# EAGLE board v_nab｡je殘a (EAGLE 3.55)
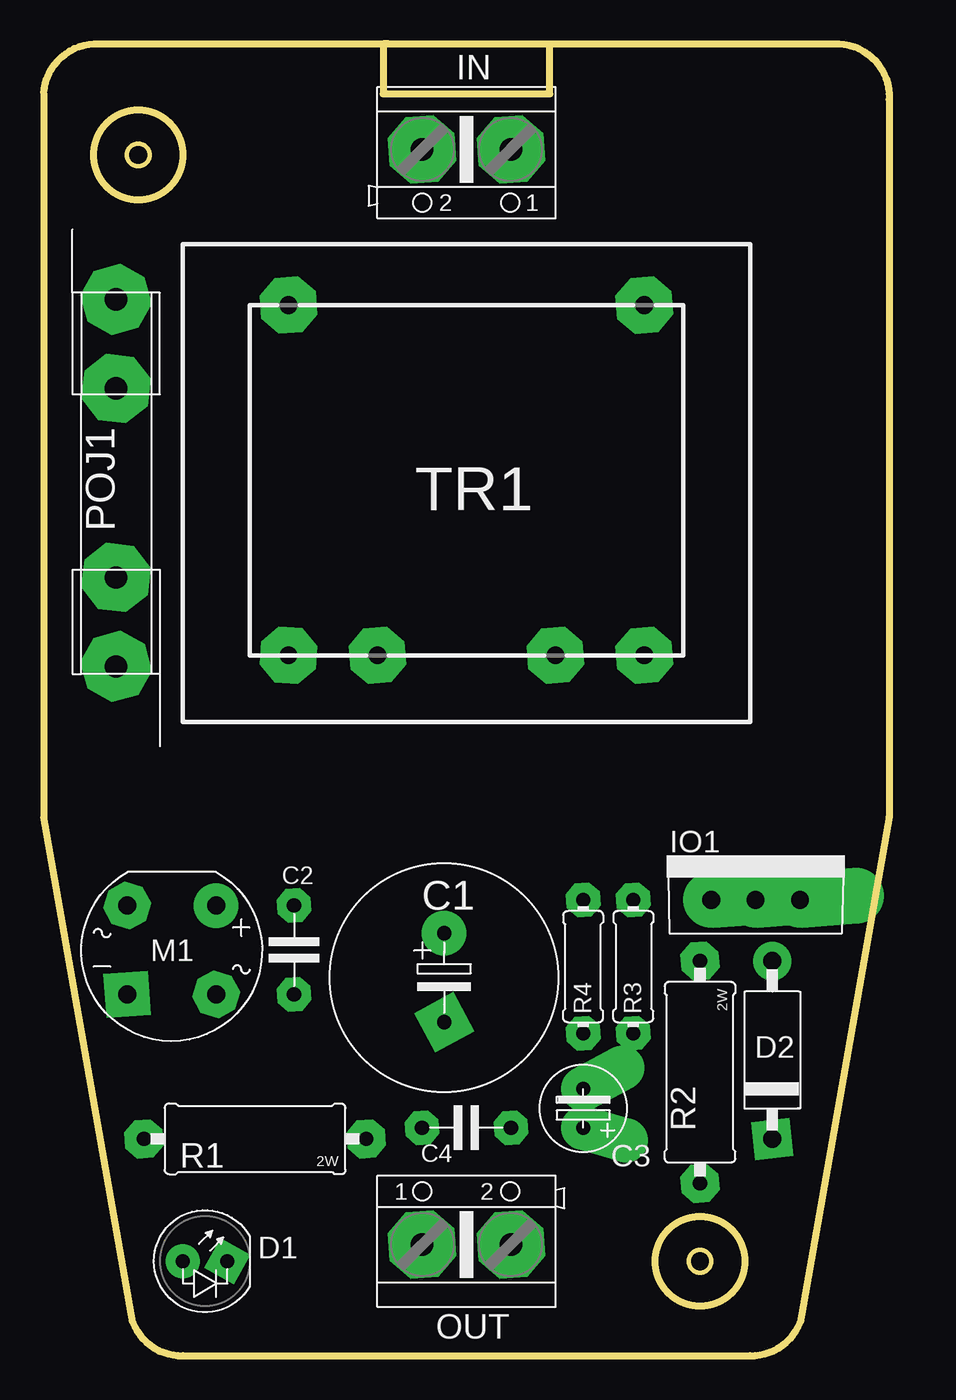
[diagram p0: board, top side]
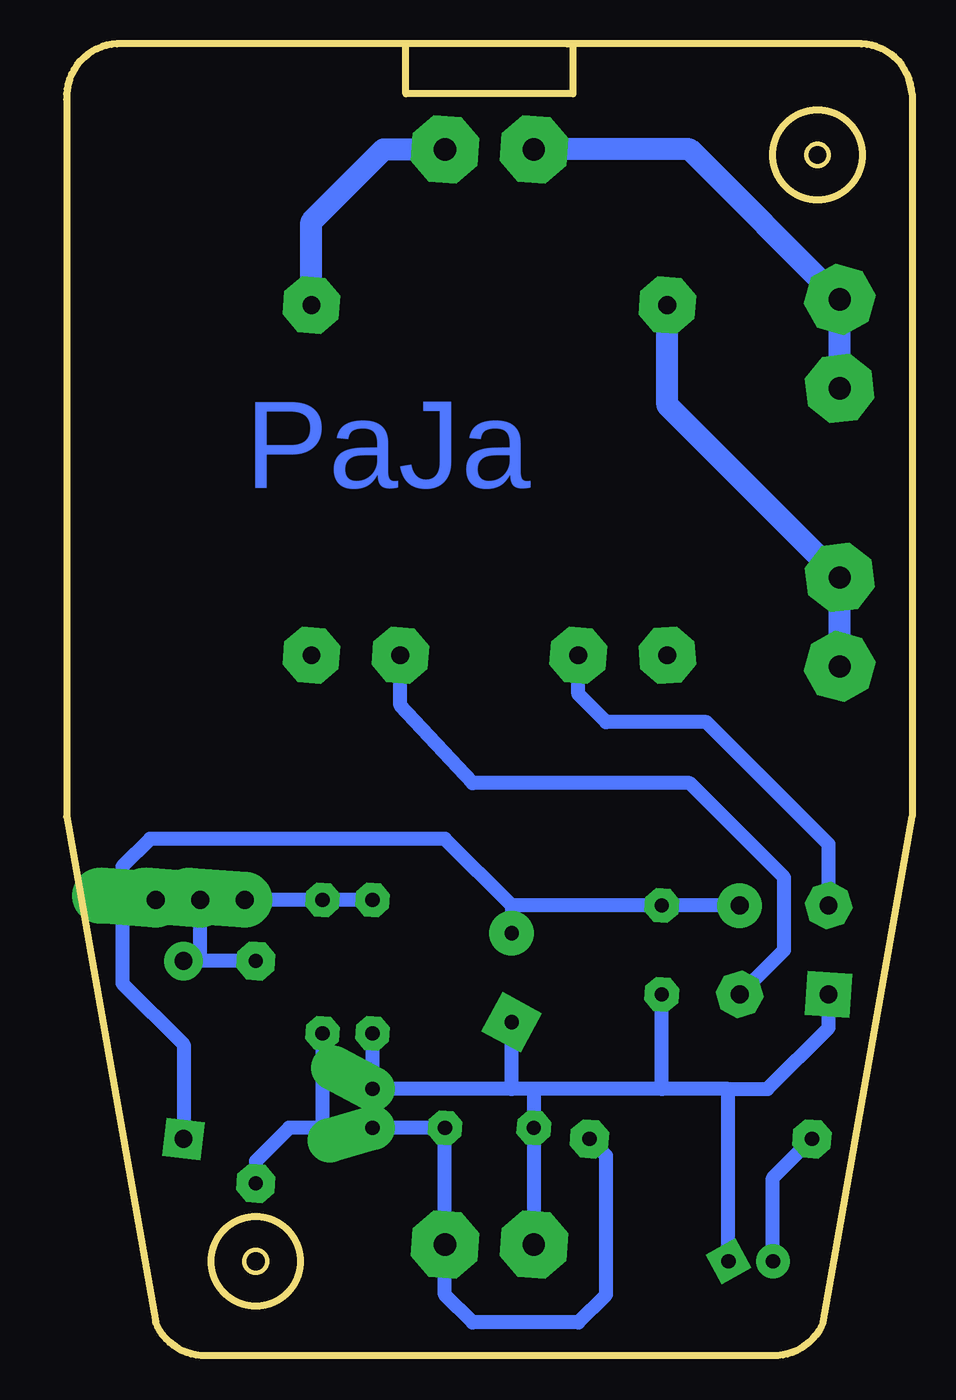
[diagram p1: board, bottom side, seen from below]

Size 48.26 x 74.93 mm. Coordinates in mm from the lower left corner, seen from the top.
Outline: 19.68,74.93 19.37,74.93 19.37,72.07 28.89,72.07 28.89,74.93
Outline: circle at 5.4,68.58 radius 0.64
Outline: circle at 37.46,5.4 radius 0.64
Copper layers used: Bottom

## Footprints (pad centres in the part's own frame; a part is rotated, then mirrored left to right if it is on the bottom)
EL_5+ = drill 0.813 pad 2.54 round:  -2.54,0 | drill 0.813 pad 2.54 square:  2.54,0
5 = drill 0.813 pad 1.93 octagon:  -2.54,0;  2.54,0
EL_2 = drill 0.813 pad 2.54 offset:  0,0;  2.223,0
D_5 = drill 0.813 pad 1.93 square:  1.27,0 | drill 0.813 pad 1.93 round:  -1.27,0
10 = drill 1.016 pad 2.184 square:  5.08,0 | drill 1.016 pad 2.184 round:  -5.08,0
K500/2 = drill 1.27 pad 3.81 octagon:  -2.54,0;  2.54,0
-220S = drill 1.016 pad 3.2 offset:  -2.54,0;  0,0;  2.54,0
_WOM = drill 1.016 pad 2.54 octagon:  -2.54,2.54;  2.54,-2.54 | drill 1.016 pad 2.54 square:  2.54,2.54 | drill 1.016 pad 2.54 round:  -2.54,-2.54
JIST_1 = drill 1.27 pad 3.81 octagon:  -10.477,0;  -5.397,0;  5.397,0;  10.477,0
_2W = drill 0.813 pad 2.184 octagon:  -6.35,0;  6.35,0
7,5 = drill 0.813 pad 1.93 octagon:  -3.81,0;  3.81,0
HEI304 = drill 1.016 pad 3.2 octagon:  -5.08,-9.842;  5.08,-9.842;  -10.16,10.16;  10.16,10.16;  10.16,-9.842;  -10.16,-9.842

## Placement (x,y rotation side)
C1  1000M/25V  [EL_5+]  22.86,21.59 270 top
C2  100n  [5]  14.29,23.18 270 top
C3  4M7  [EL_2]  30.8,13.02 90 top
C4  100n  [5]  24.13,13.02 180 top
D1  zel  [D_5]  9.21,5.4 0 top
D2  1N4007  [10]  41.59,17.46 270 top
IN  230V  [K500/2]  24.13,68.9 180 top
IO1  LM317T  [-220S]  40.64,26.03 0 top
M1  B250C1500  [_WOM]  7.3,23.18 180 top
OUT  11V/60mA  [K500/2]  24.13,6.35 0 top
POJ1  200mA  [JIST_1]  4.13,49.85 270 top
R1  1k5/2W  [_2W]  12.06,12.38 180 top
R2  15/2W  [_2W]  37.46,16.19 270 top
R3  220  [7,5]  33.66,22.22 270 top
R4  1k8  [7,5]  30.8,22.22 90 top
TR1  TRHEI304-1x12  [HEI304]  24.13,49.85 0 top
U$1  [KPZ3]  24.13,30.8 0 top

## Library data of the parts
C1 C3 = #PaJa_C-
C2 D1 IN M1 POJ1 TR1 = #PaJa_89
C4 D2 IO1 OUT R3 R4 = #PaJa_91
R1 R2 = #PaJa_R
U$1 = #PaJa_9

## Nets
GND: C1. C2. C3. C4. D1. M1. OUT. R4.
IN: C1. C2. D2. IO1. M1.
N$1: IO1. R3. R4.
N$2: M1. TR1.
N$3: M1. TR1.
N$4: POJ1. TR1.
N$5: D1. R1.
N$6: IN. POJ1.
N$7: D2. IO1. R2.
N$8: IN. TR1.
N$11: C3. C4. OUT. R1. R2. R3.

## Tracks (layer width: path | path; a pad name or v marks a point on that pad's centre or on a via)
GND
  Bottom 0.813: 10.48,15.24 8.25,15.24 4.76,18.73 4.76,20.64 | 10.48,15.24 14.29,15.24 | 14.29,15.24 21.59,15.24 | 21.59,6.35 C4. 21.59,15.24 | 21.59,15.24 22.86,15.24 | 22.86,15.24 C3. 30.8,18.41 30.48,18.41 | 22.86,15.24 C1. | 14.29,15.24 C2. | 10.48,5.4 10.48,15.24
IN
  Bottom 0.813: 22.86,25.72 14.29,25.72 M1. | 22.86,25.72 26.67,29.53 43.5,29.53 45.09,27.94 45.09,26.03 | 22.86,25.72 22.86,24.13 | 45.09,26.03 IO1. | 41.59,12.38 41.59,17.78 45.09,21.27 45.09,26.03
N$1
  Bottom 0.813: R4. 33.66,26.03 38.1,26.03
N$2
  Bottom 0.813: 19.05,40 19.05,37.78 17.46,36.2 11.75,36.2 4.76,29.21 4.76,25.72
N$3
  Bottom 0.813: 29.21,40 29.21,37.15 25.08,32.7 12.7,32.7 7.3,27.3 7.3,23.18 9.84,20.64
N$4
  Bottom 1.27: POJ1. 4.13,44.45 13.97,54.29 13.97,60.01
N$5
  Bottom 0.813: 7.94,5.08 D1. 7.94,10.16 R1.
N$6
  Bottom 1.27: IN. 12.7,68.9 4.13,60.32 4.13,56.51
N$7
  Bottom 0.813: 40.64,22.54 40.64,26.03 | 40.64,22.54 D2. | 37.46,22.54 40.64,22.54
N$8
  Bottom 1.27: 26.67,68.9 30.16,68.9 34.29,64.77 34.29,60.01
N$11
  Bottom 0.813: 33.66,13.02 R3. | 33.66,13.02 30.8,13.02 26.67,13.02 OUT. 26.67,3.49 25.08,1.9 19.05,1.9 17.46,3.49 17.46,11.43 18.41,12.38 | R2. 37.46,11.11 35.56,13.02 33.66,13.02

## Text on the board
Bottom: PaJa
